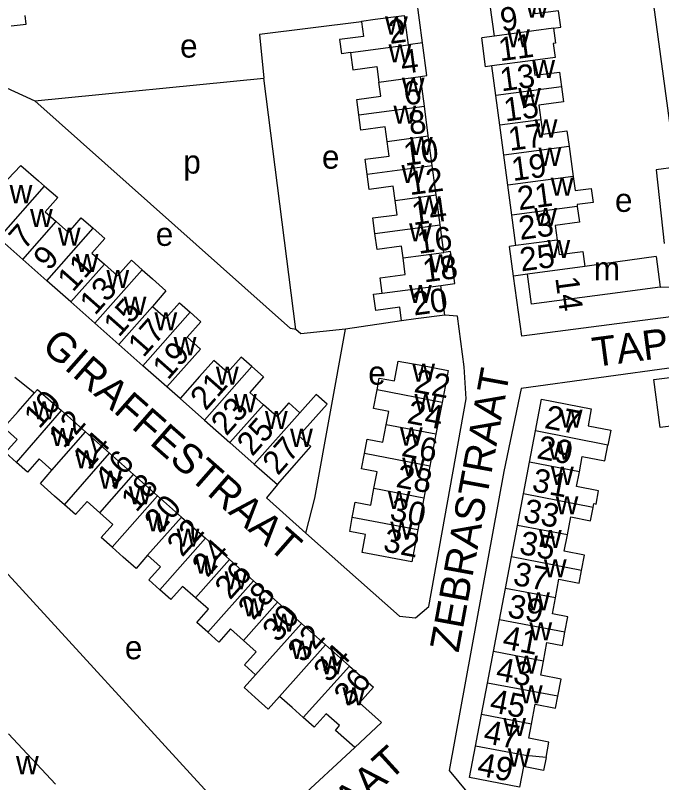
# Model space of a CAD drawing. Extents: x 162667 to 164645, y 379003 to 382150.
# Drawn here: x 163364 to 163473.8, y 381018.3 to 381148.7 of the extents above; entities that cross this region are included whole.
import ezdxf

# ---------------------------------------------------------------- set-up
doc = ezdxf.new("R2010")
doc.units = 0
for name, color, linetype in [('BLT_Basislijn', 7, 'Continuous'), ('BLT_Bebouwing', 7, 'Continuous'), ('BLT_Centroide', 7, 'Continuous'), ('BLT_Huisnummer', 7, 'Continuous'), ('BLT_Huisnummer_ tussenligend', 7, 'Continuous'), ('BLT_Onderverdeling_panden', 7, 'Continuous'), ('BLT_Straatnaam', 7, 'Continuous')]:
    doc.layers.add(name, color=color, linetype=linetype)

msp = doc.modelspace()

# ---------------------------------------------------------------- linework, layer by layer
at = {"layer": 'BLT_Basislijn'}
for p, q in [((163433.19, 381144.02), (163431.02, 381160.15)), ((163476.23, 381122.88), (163471.97, 381154.32)), ((163367.31, 381134.19), (163406.21, 381138.04)), ((163411.65, 381095.33), (163406.21, 381138.04)), ((163473.56, 381102.51), (163475.18, 381102.55)), ((163429.62, 381096.8), (163420.09, 381095.39)), ((163363.88, 381087.21), (163367.25, 381084.57)), ((163391.98, 381083.56), (163389.74, 381085.54)), ((163350, 381067.6), (163404.28, 381008.28)), ((163421.66, 381024.26), (163404.28, 381008.28))]:
    msp.add_line(p, q, dxfattribs=at)
for points in [[(163422.81, 381147.62), (163405.44, 381145.46), (163406.21, 381138.04)], [(163361.73, 381136.74), (163367.31, 381134.19)], [(163411.65, 381095.33), (163410.75, 381095.49), (163367.31, 381134.19)], [(163476.23, 381122.88), (163472.91, 381122.44), (163474.24, 381109.92)], [(163506.35, 381101.46), (163450.08, 381094.2), (163448.63, 381104.37)], [(163413.37, 381060.71), (163429.26, 381046.58), (163432, 381046.33), (163434.26, 381048.24), (163440.58, 381083.53), (163440.26, 381088.98), (163439.1, 381097.55), (163436.96, 381097.77)], [(163420.09, 381095.39), (163412.5, 381094.57), (163411.65, 381095.33)], [(163413.37, 381060.71), (163414.87, 381066.62), (163420.09, 381095.39)], [(163477.24, 381089.02), (163476.32, 381088.9), (163449.95, 381085.27), (163447.02, 381071.2), (163437.7, 381020.39), (163475.54, 380974.72)], [(163408.51, 381068.98), (163406.68, 381066.73), (163413.37, 381060.71)]]:
    msp.add_lwpolyline(points, dxfattribs=at)
at = {"layer": 'BLT_Bebouwing'}
for p, q in [((163445.38, 381145.18), (163444.69, 381150.41)), ((163365.79, 381147.19), (163365.62, 381148.7)), ((163363.24, 381146.89), (163365.79, 381147.19)), ((163445.38, 381145.18), (163443.23, 381144.89)), ((163443.89, 381139.96), (163443.23, 381144.89)), ((163433.19, 381144.02), (163430.74, 381143.69)), ((163420.94, 381142.39), (163419.41, 381142.18)), ((163444.98, 381140.11), (163443.89, 381139.96)), ((163445.65, 381135.06), (163444.98, 381140.11)), ((163433.49, 381133.28), (163432.82, 381138.3)), ((163446.32, 381130.04), (163445.65, 381135.06)), ((163434.16, 381128.2), (163433.49, 381133.28)), ((163447, 381124.92), (163446.32, 381130.04)), ((163434.83, 381123.16), (163434.16, 381128.2)), ((163447.68, 381119.85), (163447, 381124.92)), ((163435.5, 381118.17), (163434.83, 381123.16)), ((163448.35, 381114.76), (163447.68, 381119.85)), ((163436.17, 381113.07), (163435.5, 381118.17)), ((163449.04, 381109.58), (163448.35, 381114.76)), ((163436.79, 381108.41), (163436.17, 381113.07)), ((163365.22, 381107.22), (163361.13, 381110.83)), ((163449.04, 381109.58), (163447.96, 381109.44)), ((163448.63, 381104.37), (163447.96, 381109.44)), ((163369.31, 381103.6), (163365.22, 381107.22)), ((163472.87, 381107.69), (163463.95, 381106.46)), ((163472.87, 381107.69), (163473.56, 381102.51)), ((163463.95, 381106.46), (163460.77, 381106.02)), ((163451.04, 381104.69), (163448.63, 381104.37)), ((163373.39, 381099.99), (163369.31, 381103.6)), ((163436.96, 381097.77), (163436.29, 381102.81)), ((163473.56, 381102.51), (163464.63, 381101.32)), ((163424.86, 381101.29), (163426.3, 381101.48)), ((163377.48, 381096.38), (163373.39, 381099.99)), ((163381.57, 381092.76), (163377.48, 381096.38)), ((163385.65, 381089.15), (163381.57, 381092.76)), ((163389.74, 381085.54), (163385.65, 381089.15)), ((163391.98, 381083.56), (163396.11, 381079.92)), ((163436.49, 381082.93), (163435.46, 381077.51)), ((163371.84, 381081.52), (163375.92, 381077.9)), ((163396.11, 381079.92), (163400.44, 381076.1)), ((163375.92, 381077.9), (163380, 381074.28)), ((163435.46, 381077.51), (163434.43, 381072.09)), ((163451.34, 381072.74), (163452.36, 381078.1)), ((163400.44, 381076.1), (163404.58, 381072.44)), ((163380, 381074.28), (163384.07, 381070.67)), ((163404.58, 381072.44), (163408.51, 381068.98)), ((163434.43, 381072.09), (163433.4, 381066.67)), ((163450.32, 381067.38), (163451.34, 381072.74)), ((163384.07, 381070.67), (163388.15, 381067.05)), ((163388.15, 381067.05), (163392.23, 381063.43)), ((163433.4, 381066.67), (163432.38, 381061.25)), ((163449.3, 381062.02), (163450.32, 381067.38)), ((163392.23, 381063.43), (163396.3, 381059.82)), ((163448.28, 381056.66), (163449.3, 381062.02)), ((163396.3, 381059.82), (163400.38, 381056.2)), ((163400.38, 381056.2), (163404.46, 381052.58)), ((163447.26, 381051.3), (163448.28, 381056.66)), ((163404.46, 381052.58), (163408.53, 381048.97)), ((163446.24, 381045.95), (163447.26, 381051.3)), ((163408.53, 381048.97), (163412.61, 381045.35)), ((163445.21, 381040.59), (163446.24, 381045.95)), ((163412.61, 381045.35), (163416.69, 381041.73)), ((163416.69, 381041.73), (163420.77, 381038.11)), ((163444.19, 381035.23), (163445.21, 381040.59)), ((163443.17, 381029.87), (163444.19, 381035.23)), ((163442.15, 381024.51), (163443.17, 381029.87)), ((163370.82, 381018.03), (163362.83, 381026.58))]:
    msp.add_line(p, q, dxfattribs=at)
for points in [[(163455.45, 381146.52), (163456.68, 381146.68), (163456.31, 381149.49), (163452.32, 381148.96), (163452, 381151.38)], [(163422.81, 381147.62), (163423.14, 381145.13), (163419.09, 381144.59), (163419.41, 381142.18)], [(163422.81, 381147.62), (163422.79, 381147.73), (163425.12, 381148.04), (163430.08, 381148.7), (163430.74, 381143.69)], [(163455.45, 381146.52), (163455.79, 381143.95), (163455.4, 381143.9), (163455.72, 381141.54), (163451.94, 381141.04), (163451.94, 381141.04)], [(163432.82, 381138.3), (163433.93, 381138.45), (163433.19, 381144.02)], [(163420.94, 381142.39), (163421.33, 381139.46), (163425.41, 381140), (163425.76, 381137.36)], [(163451.94, 381141.04), (163452.28, 381138.52), (163456.44, 381139.07), (163456.77, 381136.55)], [(163422.36, 381131.8), (163422.01, 381134.41), (163426.08, 381134.95), (163425.76, 381137.36)], [(163456.77, 381136.55), (163457.12, 381133.98), (163452.96, 381133.42), (163453.29, 381130.97)], [(163427.17, 381127.27), (163426.84, 381129.75), (163422.71, 381129.2), (163422.36, 381131.8)], [(163453.29, 381130.97), (163453.61, 381128.51), (163457.72, 381129.06), (163458.07, 381126.39)], [(163423.76, 381121.69), (163423.42, 381124.25), (163427.5, 381124.79), (163427.17, 381127.27)], [(163458.07, 381126.39), (163458.75, 381121.32)], [(163362.72, 381120.86), (163364.88, 381123.2), (163367.9, 381120.58), (163368.95, 381119.66)], [(163428.52, 381117.24), (163428.2, 381119.67), (163424.1, 381119.12), (163423.76, 381121.69)], [(163458.75, 381121.32), (163459.11, 381118.93), (163461.84, 381119.29), (163462.15, 381116.92), (163459.43, 381116.56), (163459.47, 381116.24)], [(163368.95, 381119.66), (163371.17, 381117.73), (163369.03, 381115.33), (163370.9, 381113.64)], [(163425.08, 381111.6), (163424.73, 381114.26), (163428.84, 381114.81), (163428.52, 381117.24)], [(163459.47, 381116.24), (163459.83, 381113.54), (163455.71, 381113), (163456.04, 381110.51)], [(163370.9, 381113.64), (163372.98, 381111.8), (163375.16, 381114.26), (163377.18, 381112.51)], [(163377.18, 381112.51), (163379.17, 381110.77), (163376.99, 381108.31), (163379.1, 381106.44)], [(163429.86, 381107.49), (163429.6, 381109.48), (163425.44, 381108.93), (163425.08, 381111.6)], [(163456.04, 381110.51), (163456.37, 381108.03), (163460.43, 381108.57), (163460.77, 381106.02)], [(163436.29, 381102.81), (163438.64, 381103.12), (163437.92, 381108.56), (163436.79, 381108.41)], [(163379.1, 381106.44), (163381.36, 381104.44), (163383.69, 381107.07), (163385.51, 381105.46)], [(163426.3, 381101.48), (163425.96, 381104.08), (163430.24, 381104.65), (163429.86, 381107.49)], [(163385.51, 381105.46), (163387.27, 381103.91), (163389.55, 381101.9), (163387.28, 381099.23)], [(163464.63, 381101.32), (163451.72, 381099.6), (163451.04, 381104.69)], [(163429.62, 381096.8), (163429.32, 381099.1), (163425.22, 381098.55), (163424.86, 381101.29)], [(163387.28, 381099.23), (163389.54, 381097.23), (163391.86, 381099.85), (163393.69, 381098.24)], [(163393.69, 381098.24), (163395.49, 381096.64), (163393.15, 381093.99), (163395.43, 381091.97), (163393.05, 381089.28), (163389.74, 381085.54)], [(163436.96, 381097.77), (163432.01, 381097.11), (163429.62, 381096.8)], [(163404.14, 381089.02), (163402.33, 381090.61), (163400.02, 381087.99), (163397.69, 381090.04), (163395.29, 381087.31), (163391.98, 381083.56)], [(163404.14, 381089.02), (163406.13, 381087.26), (163403.8, 381084.6), (163406.15, 381082.52)], [(163425.44, 381085.03), (163425.82, 381087.05), (163428.41, 381086.56), (163429.06, 381089.95), (163432.61, 381089.28), (163437.52, 381088.35), (163436.49, 381082.93)], [(163367.25, 381084.57), (163367.76, 381085.14), (163371.84, 381081.52)], [(163427, 381079.12), (163427.43, 381081.38), (163424.84, 381081.87), (163425.44, 381085.03)], [(163364.18, 381072.73), (163362.31, 381074.39), (163364.3, 381076.63), (163362.01, 381078.66), (163364.44, 381081.4), (163367.25, 381084.57)], [(163408.51, 381068.98), (163411.82, 381072.73), (163414.2, 381075.43), (163412.15, 381077.23), (163416.96, 381082.64), (163415.11, 381084.28), (163412.35, 381081.17)], [(163412.35, 381081.17), (163410.48, 381082.83), (163408.43, 381080.52), (163406.15, 381082.52)], [(163452.36, 381078.1), (163453.38, 381083.45), (163461.86, 381081.84), (163461.31, 381078.94), (163465.15, 381078.21), (163464.66, 381075.65)], [(163423.3, 381074.21), (163423.78, 381076.66), (163426.44, 381076.19), (163427, 381079.12), (163427, 381079.12)], [(163459.83, 381071.13), (163460.32, 381073.73), (163464.16, 381073), (163464.66, 381075.65)], [(163370.16, 381071.42), (163368.04, 381073.31), (163366.05, 381071.07), (163364.18, 381072.73)], [(163424.92, 381068.28), (163425.46, 381071.14), (163422.8, 381071.65), (163423.3, 381074.21)], [(163372.3, 381065.51), (163370.61, 381067.01), (163368.24, 381069.12), (163370.16, 381071.42)], [(163462.18, 381065.06), (163462.3, 381065.72), (163462.68, 381065.65), (163463.1, 381067.89), (163459.35, 381068.6), (163459.83, 381071.13)], [(163421.24, 381063.37), (163421.7, 381065.96), (163424.39, 381065.48), (163424.92, 381068.28)], [(163378.31, 381064.18), (163376.16, 381066.09), (163374.17, 381063.85), (163372.3, 381065.51)], [(163380.43, 381058.29), (163378.56, 381059.95), (163380.54, 381062.19), (163378.31, 381064.18)], [(163457.79, 381060.41), (163458.37, 381063.46), (163461.75, 381062.81), (163462.18, 381065.06)], [(163432.38, 381061.25), (163431.35, 381055.83), (163422.91, 381057.43), (163423.49, 381060.49), (163420.81, 381061), (163421.24, 381063.37)], [(163460.21, 381054.37), (163460.71, 381056.98), (163457.26, 381057.64), (163457.79, 381060.41)], [(163386.46, 381056.94), (163384.49, 381054.68), (163382.29, 381056.63), (163380.43, 381058.29)], [(163388.55, 381051.08), (163386.68, 381052.74), (163388.67, 381054.98), (163386.46, 381056.94)], [(163455.76, 381049.69), (163456.36, 381052.88), (163459.81, 381052.22), (163460.21, 381054.37)], [(163394.61, 381049.7), (163392.41, 381051.66), (163390.42, 381049.42), (163388.55, 381051.08)], [(163396.67, 381043.86), (163394.8, 381045.52), (163396.79, 381047.77), (163394.61, 381049.7)], [(163457.38, 381043.85), (163457.88, 381046.48), (163455.24, 381046.98), (163455.76, 381049.69)], [(163402.76, 381042.46), (163400.53, 381044.45), (163398.54, 381042.2), (163396.67, 381043.86)], [(163453.72, 381038.97), (163454.32, 381042.12), (163456.95, 381041.62), (163457.38, 381043.85)], [(163404.79, 381036.64), (163402.93, 381038.3), (163404.92, 381040.55), (163402.76, 381042.46)], [(163420.77, 381038.11), (163424.83, 381034.51), (163422.47, 381031.84), (163426.23, 381028.51), (163421.66, 381024.26)], [(163456.17, 381033.01), (163456.72, 381035.9), (163453.26, 381036.56), (163453.72, 381038.97)], [(163408.87, 381032.96), (163406.96, 381030.8), (163404.72, 381032.79), (163402.85, 381034.45), (163404.79, 381036.64)], [(163412.89, 381029.39), (163411.02, 381031.05), (163408.87, 381032.96)], [(163451.68, 381028.25), (163452.32, 381031.61), (163455.78, 381030.95), (163456.17, 381033.01)], [(163421.66, 381024.26), (163418.39, 381027.16), (163419.05, 381027.99), (163416.78, 381030.01), (163414.76, 381027.73), (163412.89, 381029.39)], [(163454.16, 381022.55), (163454.66, 381025.2), (163451.23, 381025.85), (163451.68, 381028.25)], [(163454.16, 381022.55), (163453.74, 381020.36), (163450.31, 381021.02), (163449.65, 381017.54), (163441.13, 381019.16), (163442.15, 381024.51)]]:
    msp.add_lwpolyline(points, dxfattribs=at)
msp.add_lwpolyline([(163472.49, 381086.79), (163475.18, 381087.15), (163476.26, 381079.02), (163473.57, 381078.66)], close=True, dxfattribs=at)
at = {"layer": 'BLT_Onderverdeling_panden'}
for p, q in [((163455.45, 381146.52), (163445.38, 381145.18)), ((163420.94, 381142.39), (163430.74, 381143.69)), ((163451.94, 381141.04), (163444.98, 381140.11)), ((163425.76, 381137.36), (163432.82, 381138.3)), ((163456.77, 381136.55), (163445.65, 381135.06)), ((163422.36, 381131.8), (163433.49, 381133.28)), ((163453.29, 381130.97), (163446.32, 381130.04)), ((163427.17, 381127.27), (163434.16, 381128.2)), ((163458.07, 381126.39), (163447, 381124.92)), ((163423.76, 381121.69), (163434.83, 381123.16)), ((163458.75, 381121.32), (163447.68, 381119.85)), ((163361.13, 381110.83), (163368.95, 381119.66)), ((163428.52, 381117.24), (163435.5, 381118.17)), ((163459.47, 381116.24), (163448.35, 381114.76)), ((163365.22, 381107.22), (163370.9, 381113.64)), ((163369.31, 381103.6), (163377.18, 381112.51)), ((163425.08, 381111.6), (163436.17, 381113.07)), ((163456.04, 381110.51), (163449.04, 381109.58)), ((163429.86, 381107.49), (163436.79, 381108.41)), ((163373.39, 381099.99), (163379.1, 381106.44)), ((163460.77, 381106.02), (163451.04, 381104.69)), ((163377.48, 381096.38), (163385.51, 381105.46)), ((163426.3, 381101.48), (163436.29, 381102.81)), ((163381.57, 381092.76), (163387.28, 381099.23)), ((163385.65, 381089.15), (163393.69, 381098.24)), ((163396.11, 381079.92), (163404.14, 381089.02)), ((163436.49, 381082.93), (163425.44, 381085.03)), ((163400.44, 381076.1), (163406.15, 381082.52)), ((163364.18, 381072.73), (163371.84, 381081.52)), ((163404.58, 381072.44), (163412.35, 381081.17)), ((163435.46, 381077.51), (163427, 381079.12)), ((163370.16, 381071.42), (163375.92, 381077.9)), ((163464.66, 381075.65), (163452.36, 381078.1)), ((163372.3, 381065.51), (163380, 381074.28)), ((163434.43, 381072.09), (163423.3, 381074.21)), ((163459.83, 381071.13), (163451.34, 381072.74)), ((163378.31, 381064.18), (163384.07, 381070.67)), ((163433.4, 381066.67), (163424.92, 381068.28)), ((163380.43, 381058.29), (163388.15, 381067.05)), ((163462.18, 381065.06), (163450.32, 381067.38)), ((163386.46, 381056.94), (163392.23, 381063.43)), ((163432.38, 381061.25), (163421.24, 381063.37)), ((163457.79, 381060.41), (163449.3, 381062.02)), ((163388.55, 381051.08), (163396.3, 381059.82)), ((163394.61, 381049.7), (163400.38, 381056.2)), ((163460.21, 381054.37), (163448.28, 381056.66)), ((163396.67, 381043.86), (163404.46, 381052.58)), ((163455.76, 381049.69), (163447.26, 381051.3)), ((163402.76, 381042.46), (163408.53, 381048.97)), ((163457.38, 381043.85), (163446.24, 381045.95)), ((163404.79, 381036.64), (163412.61, 381045.35)), ((163408.87, 381032.96), (163416.69, 381041.73)), ((163453.72, 381038.97), (163445.21, 381040.59)), ((163412.89, 381029.39), (163420.77, 381038.11)), ((163456.17, 381033.01), (163444.19, 381035.23)), ((163451.68, 381028.25), (163443.17, 381029.87))]:
    msp.add_line(p, q, dxfattribs=at)
msp.add_lwpolyline([(163454.16, 381022.55), (163450.67, 381022.89), (163442.15, 381024.51)], dxfattribs=at)

# ---------------------------------------------------------------- texts
at = {"layer": 'BLT_Centroide'}
for s, p in [('w', (163450.72, 381148.28)), ('w', (163426.8, 381145.44)), ('w', (163447.55, 381143.25)), ('e', (163391.97, 381141.52)), ('w', (163427.4, 381140.69)), ('w', (163451.84, 381138.06)), ('w', (163429.66, 381135.06)), ('w', (163449.43, 381133.28)), ('w', (163428.23, 381130.28)), ('w', (163452.23, 381127.94)), ('w', (163431.04, 381124.94)), ('e', (163416.08, 381122.64)), ('w', (163452.88, 381123.12)), ('p', (163392.52, 381121.81)), ('w', (163429.59, 381120.19)), ('w', (163454.96, 381118.03)), ('w', (163363, 381116.78)), ('w', (163432.38, 381114.88)), ('e', (163465.88, 381115.3)), ('w', (163366.47, 381112.73)), ('w', (163452.16, 381112.91)), ('w', (163371.2, 381109.56)), ('e', (163387.84, 381109.52)), ('w', (163430.9, 381110.28)), ('w', (163454.4, 381107.44)), ('w', (163374.23, 381105.06)), ('w', (163434.29, 381105.03)), ('m', (163462.29, 381103.66)), ('w', (163379.45, 381102.36)), ('w', (163430.87, 381099.81)), ('w', (163382.38, 381097.8)), ('w', (163387.62, 381095.16)), ('w', (163390.88, 381090.94)), ('w', (163398.06, 381085.92)), ('e', (163423.95, 381085.93)), ('w', (163431.43, 381086.44)), ('w', (163401.12, 381081.25)), ('w', (163431.8, 381081.28)), ('w', (163366.92, 381080.03)), ('w', (163406.39, 381078.39)), ('w', (163456.5, 381078.61)), ('w', (163370.05, 381075.5)), ('w', (163410.67, 381075.36)), ('w', (163429.34, 381075.59)), ('w', (163454.52, 381073.18)), ('w', (163374.12, 381071.73)), ('w', (163429.73, 381070.44)), ('w', (163455.01, 381068.91)), ('w', (163378.19, 381068.25)), ('w', (163383.23, 381065.59)), ('w', (163427.27, 381064.78)), ('w', (163455.8, 381063.91)), ('w', (163386.33, 381061.02)), ('w', (163391.38, 381058.38)), ('w', (163427.7, 381059.59)), ('w', (163452.97, 381058.19)), ('w', (163394.47, 381053.8)), ('w', (163453.8, 381053.19)), ('w', (163399.53, 381051.16)), ('w', (163450.95, 381047.56)), ('w', (163402.61, 381046.55)), ('w', (163407.69, 381043.94)), ('w', (163451.34, 381042.47)), ('e', (163382.58, 381039.27)), ('w', (163410.73, 381039.33)), ('w', (163415.84, 381036.72)), ('w', (163448.91, 381036.81)), ('w', (163419.56, 381031.45)), ('w', (163449.73, 381031.75)), ('w', (163446.89, 381026.22)), ('w', (163447.68, 381021.03)), ('w', (163364.08, 381019.73))]:
    msp.add_text(s, height=4, dxfattribs=at).set_placement(p)
at = {"layer": 'BLT_Huisnummer'}
for s, rotation, p in [('9', 7.6608, (163446.65, 381145.93)), ('2', 7.5751, (163427.65, 381143.83)), ('13', 7.6608, (163446.59, 381135.77)), ('6', 7.5751, (163430.24, 381133.37)), ('17', 7.6608, (163448.01, 381125.66)), ('10', 7.5751, (163430.2, 381123.11)), ('21', 7.6608, (163449.56, 381115.58)), ('14', 7.5751, (163431.59, 381113.02)), ('25', 7.6608, (163449.96, 381105.17)), ('9', 48.5153, (163369.67, 381105.13)), ('13', 48.5153, (163377.53, 381097.58)), ('14', 277.5873, (163455.73, 381104.1)), ('20', 7.5751, (163431.74, 381097.68)), ('17', 48.5153, (163385.73, 381090.41)), ('21', 48.5153, (163396.33, 381081.37)), ('22', 349.239, (163431.58, 381084.71)), ('10', 48.3824, (163368.03, 381078.28)), ('27', 349.239, (163453.75, 381078.59)), ('14', 48.3824, (163376.4, 381071.25)), ('27', 48.5153, (163408.59, 381070.36)), ('26', 349.2401, (163429.43, 381073.84)), ('18', 48.3824, (163384.53, 381064.11)), ('31', 349.239, (163451.61, 381067.86)), ('22', 48.3824, (163392.33, 381056.49)), ('32', 349.2397, (163426.32, 381057.65)), ('35', 349.239, (163449.45, 381057.21)), ('26', 48.3824, (163400.47, 381049.22)), ('39', 349.239, (163447.45, 381046.47)), ('30', 48.3824, (163408.57, 381041.97)), ('43', 349.239, (163445.48, 381035.74)), ('36', 48.3824, (163420.72, 381031)), ('49', 349.239, (163442.29, 381019.55))]:
    msp.add_text(s, height=4, rotation=rotation, dxfattribs=at).set_placement(p)
at = {"layer": 'BLT_Huisnummer_ tussenligend'}
for s, rotation, p in [('11', 7.6608, (163446.35, 381140.89)), ('4', 7.5751, (163429.73, 381138.72)), ('15', 7.6608, (163447.24, 381130.63)), ('8', 7.5751, (163431.06, 381128.39)), ('19', 7.6608, (163448.55, 381120.53)), ('12', 7.5751, (163431.02, 381118.13)), ('23', 7.6608, (163449.77, 381110.52)), ('7', 48.5153, (163365.5, 381108.7)), ('16', 7.5751, (163432.52, 381108.16)), ('11', 48.5153, (163373.75, 381101.54)), ('18', 7.5751, (163433.46, 381103.29)), ('15', 48.5153, (163381.58, 381093.87)), ('19', 48.5153, (163389.91, 381086.59)), ('23', 48.5153, (163399.85, 381077.09)), ('24', 349.239, (163430.38, 381079.45)), ('12', 48.3824, (163372.21, 381074.93)), ('25', 48.5153, (163404.25, 381073.61)), ('29', 349.239, (163452.44, 381073.45)), ('16', 48.3824, (163380.45, 381068.12)), ('28', 349.2401, (163428.51, 381068.58)), ('20', 48.3824, (163388.5, 381060.53)), ('30', 349.2401, (163427.45, 381062.92)), ('33', 349.239, (163450.12, 381062.68)), ('24', 48.3824, (163396.6, 381053.01)), ('37', 349.239, (163448.39, 381051.95)), ('28', 48.3824, (163404.41, 381045.75)), ('32', 48.3824, (163412.87, 381038.5)), ('41', 349.239, (163446.59, 381041.12)), ('34', 48.3824, (163417.26, 381035.13)), ('45', 349.239, (163444.43, 381030.34)), ('47', 349.239, (163443.37, 381025.08))]:
    msp.add_text(s, height=4, rotation=rotation, dxfattribs=at).set_placement(p)
at = {"layer": 'BLT_Straatnaam'}
for s, rotation, p in [('TAPIRSTRAAT', 7.5541, (163462.37, 381088.93)), ('GIRAFFESTRAAT', 318.6677, (163368.21, 381092.13)), ('ZEBRASTRAAT', 79.6091, (163439.29, 381040.28)), ('ZEBRASTRAAT', 42.2925, (163394.58, 380988.48))]:
    msp.add_text(s, height=5, rotation=rotation, dxfattribs=at).set_placement(p)

doc.saveas('drawing.dxf')
